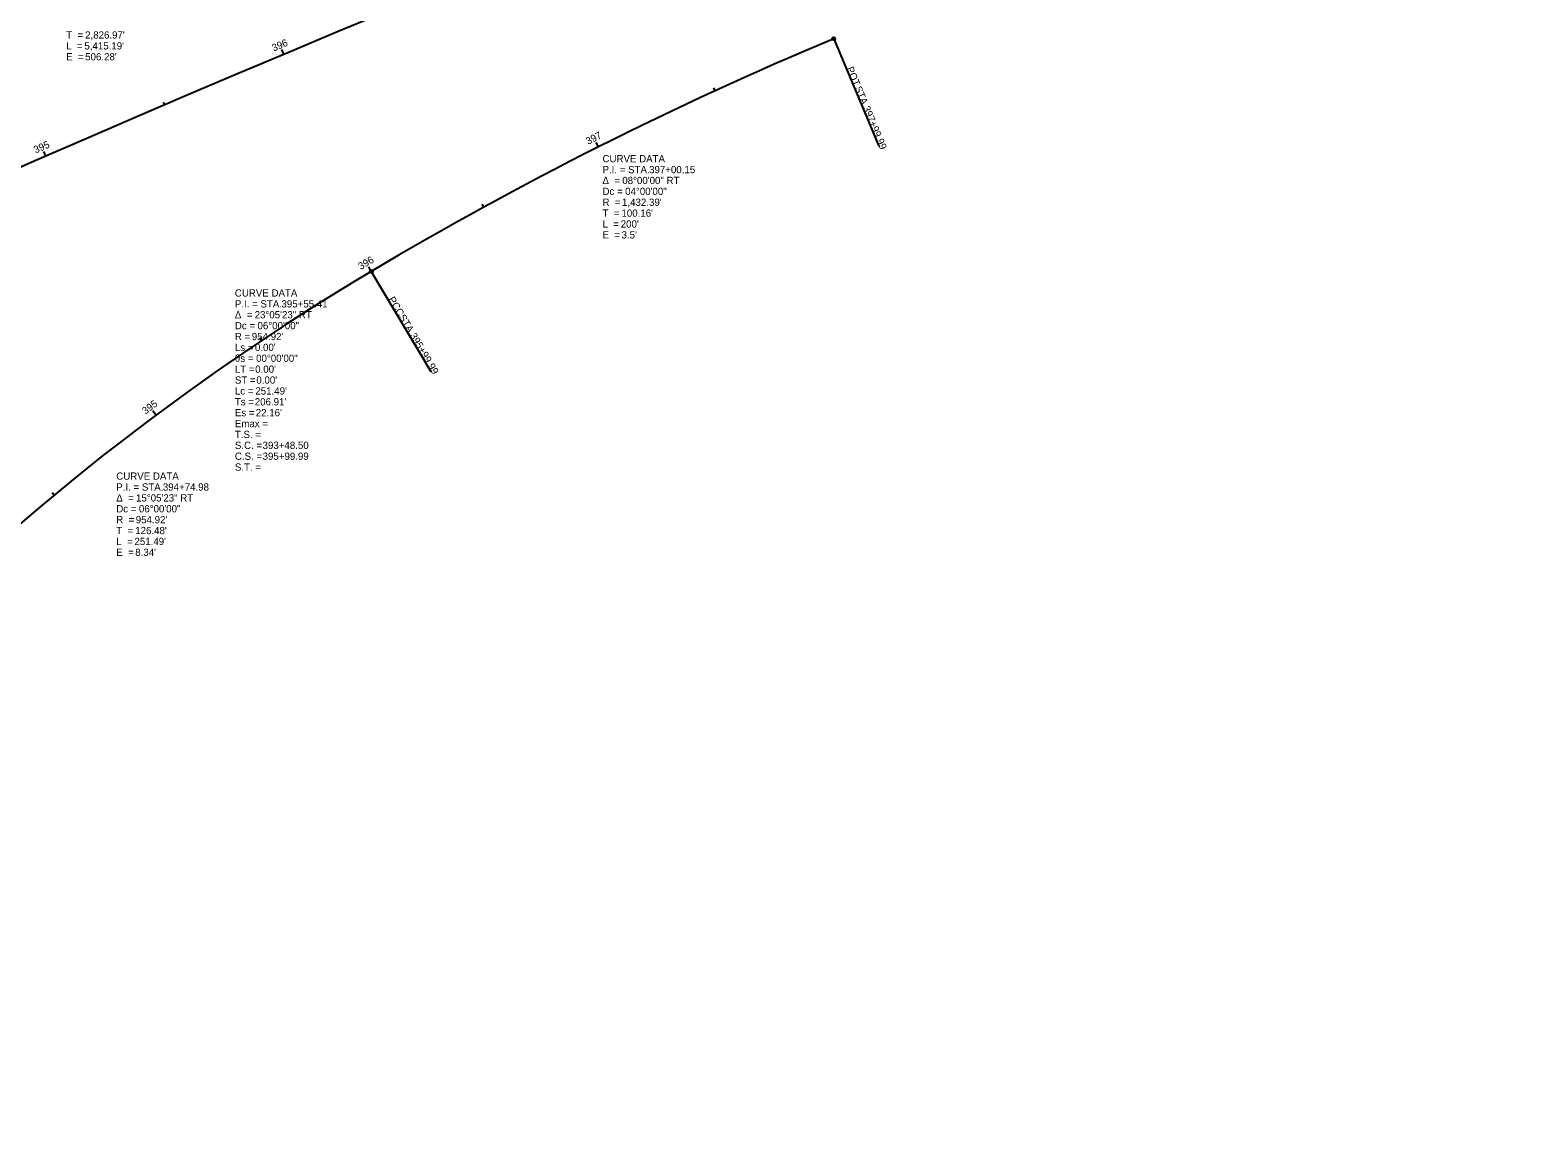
# Model space of a CAD drawing. Extents: x 2138583 to 2143699, y 639707 to 641182.
# Drawn here: x 2139980 to 2140562, y 640168 to 640590 of the extents above; entities that cross this region are included whole.
import ezdxf

# ---------------------------------------------------------------- set-up
doc = ezdxf.new("R2010")
doc.units = 0
for name, color, linetype in [('GE_X_Alignment', 7, 'Continuous'), ('GE_X_Alignment_100_Cardinal_Points', 7, 'Continuous'), ('GE_X_Alignment_100_Curve_Data', 7, 'Continuous'), ('GE_X_Alignment_100_Stations', 7, 'Continuous'), ('RW_X_CL', 7, 'Continuous'), ('RW_X_CL_100_Curve_Data', 7, 'Continuous'), ('RW_X_CL_100_Stations', 7, 'Continuous')]:
    doc.layers.add(name, color=color, linetype=linetype)

msp = doc.modelspace()

# ---------------------------------------------------------------- linework, layer by layer
at = {"layer": 'GE_X_Alignment'}
for centre, radius, start, end in [((2140843.14, 639265.57), 1432.39, 112.70421, 120.70421), ((2140599.34, 639676.11), 954.92, 120.70421, 135.79393)]:
    msp.add_arc(centre, radius, start, end, dxfattribs=at)
at = {"layer": 'GE_X_Alignment_100_Cardinal_Points'}
for p, q in [((2140290.27, 640586.96), (2140307.64, 640545.45)), ((2140111.75, 640497.16), (2140134.73, 640458.47))]:
    msp.add_line(p, q, dxfattribs=at)
for centre in [(2140290.27, 640586.96), (2140111.75, 640497.16)]:
    msp.add_circle(centre, 0.6, dxfattribs=at)
at = {"layer": 'GE_X_Alignment_100_Stations'}
for p, q in [((2140244.5, 640566.87), (2140244, 640567.96)), ((2140199.45, 640545.18), (2140198.56, 640546.97)), ((2140155.19, 640521.94), (2140154.61, 640522.99)), ((2140111.76, 640497.16), (2140110.74, 640498.88)), ((2140069.46, 640470.52), (2140068.79, 640471.52)), ((2140028.61, 640441.7), (2140027.41, 640443.3)), ((2139989.32, 640410.78), (2139988.55, 640411.7))]:
    msp.add_line(p, q, dxfattribs=at)
at = {"layer": 'RW_X_CL'}
msp.add_arc((2143034.99, 633536.97), 7639.44, 85.029584, 125.643473, dxfattribs=at)
at = {"layer": 'RW_X_CL_100_Stations'}
for p, q in [((2140078.02, 640580.93), (2140077.25, 640582.77)), ((2140031.99, 640561.43), (2140031.51, 640562.53)), ((2139986.08, 640541.62), (2139985.28, 640543.46))]:
    msp.add_line(p, q, dxfattribs=at)

# ---------------------------------------------------------------- texts
at = {"layer": 'GE_X_Alignment_100_Cardinal_Points'}
for s, rotation, p in [('POT', 292.70421, (2140295.11, 640575.5)), (' STA. ', 292.70421, (2140297.86, 640568.92)), ('397+99.99', 292.70421, (2140301.46, 640560.32)), ('PCC', 300.70421, (2140118.18, 640486.41)), (' STA. ', 300.70421, (2140121.73, 640480.42)), ('395+99.99', 300.70421, (2140126.49, 640472.41))]:
    msp.add_text(s, height=2.8, rotation=rotation, dxfattribs=at).set_placement(p)
at = {"layer": 'GE_X_Alignment_100_Curve_Data'}
for s, p in [('CURVE DATA', (2140201.01, 640539.26)), ('P.I. = STA. ', (2140201.01, 640535.06)), ('397+00.15', (2140219, 640535.06)), ('Δ  = ', (2140201.01, 640530.86)), ('Dc = ', (2140201.01, 640526.66)), ('08°00\'00" RT', (2140208.66, 640530.86)), ('04°00\'00"', (2140209.76, 640526.66)), ('R  = ', (2140201.01, 640522.46)), ("1,432.39'", (2140208.55, 640522.46)), ('T  = ', (2140201.01, 640518.26)), ("100.16'", (2140208.33, 640518.26)), ('L  = ', (2140201.01, 640514.06)), ('E  = ', (2140201.01, 640509.86)), ("200'", (2140208.05, 640514.06)), ("3.5'", (2140208.36, 640509.86)), ('CURVE DATA', (2140059.08, 640487.43)), ('P.I. = STA. ', (2140059.08, 640483.23)), ('395+55.41', (2140077.07, 640483.23)), ('Δ  = ', (2140059.08, 640479.03)), ('Dc = ', (2140059.08, 640474.83)), ('23°05\'23" RT', (2140066.73, 640479.03)), ('06°00\'00"', (2140067.83, 640474.83)), ('R = ', (2140059.08, 640470.63)), ("954.92'", (2140065.62, 640470.63)), ('θs = ', (2140059.08, 640462.23)), ('Ls = ', (2140059.08, 640466.43)), ("0.00'", (2140066.83, 640466.43)), ('00°00\'00"', (2140067.29, 640462.23)), ('LT = ', (2140059.08, 640458.03)), ("0.00'", (2140066.93, 640458.03)), ('ST = ', (2140059.08, 640453.83)), ("0.00'", (2140067.38, 640453.83)), ('Ts = ', (2140059.08, 640445.43)), ('Lc = ', (2140059.08, 640449.63)), ("206.91'", (2140066.77, 640445.43)), ("251.49'", (2140067, 640449.63)), ('Es = ', (2140059.08, 640441.23)), ("22.16'", (2140067.14, 640441.23)), ('Emax = ', (2140059.08, 640437.03)), ('T.S. = ', (2140059.08, 640432.83)), ('S.C. = ', (2140059.08, 640428.63)), ('393+48.50', (2140069.79, 640428.63)), ('C.S. = ', (2140059.08, 640424.43)), ('395+99.99', (2140069.79, 640424.43)), ('CURVE DATA', (2140013.29, 640416.74)), ('S.T. = ', (2140059.08, 640420.23)), ('P.I. = STA. ', (2140013.29, 640412.54)), ('394+74.98', (2140031.28, 640412.54)), ('Δ  = ', (2140013.29, 640408.34)), ('Dc = ', (2140013.29, 640404.14)), ('15°05\'23" RT', (2140020.93, 640408.34)), ('06°00\'00"', (2140022.03, 640404.14)), ('R  = ', (2140013.29, 640399.94)), ("954.92'", (2140020.82, 640399.94)), ('T  = ', (2140013.29, 640395.74)), ("126.48'", (2140020.61, 640395.74)), ('L  = ', (2140013.29, 640391.54)), ('E  = ', (2140013.29, 640387.34)), ("251.49'", (2140020.32, 640391.54)), ("8.34'", (2140020.63, 640387.34))]:
    msp.add_text(s, height=2.8, dxfattribs=at).set_placement(p)
at = {"layer": 'GE_X_Alignment_100_Stations'}
for s, rotation, p in [('397', 26.70382, (2140195.43, 640545.96)), ('396', 30.70383, (2140107.69, 640497.65)), ('395', 36.7037, (2140024.54, 640441.79))]:
    msp.add_text(s, height=2.8, rotation=rotation, dxfattribs=at).set_placement(p)
at = {"layer": 'RW_X_CL_100_Curve_Data'}
for s, p in [('T  = ', (2139993.95, 640587.01)), ("2,826.97'", (2140001.27, 640587.01)), ('L  = ', (2139993.95, 640582.81)), ('E  = ', (2139993.95, 640578.61)), ("5,415.19'", (2140000.98, 640582.81)), ("506.28'", (2140001.29, 640578.61))]:
    msp.add_text(s, height=2.8, dxfattribs=at).set_placement(p)
at = {"layer": 'RW_X_CL_100_Stations'}
for s, rotation, p in [('396', 22.77205, (2140074.06, 640581.98)), ('395', 23.52205, (2139982.14, 640542.63))]:
    msp.add_text(s, height=2.8, rotation=rotation, dxfattribs=at).set_placement(p)

doc.saveas('drawing.dxf')
